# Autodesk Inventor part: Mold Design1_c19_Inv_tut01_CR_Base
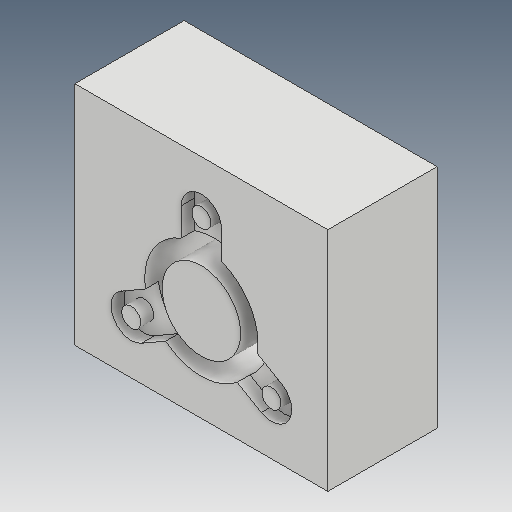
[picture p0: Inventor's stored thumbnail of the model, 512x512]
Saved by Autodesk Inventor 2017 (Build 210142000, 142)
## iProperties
Created: 2016-07
Part Number: Mold Design1_c19_Inv_tut01_CR_Base
Material: Generic
Document SubType Name: Modeling
Designer: Sandeep
Density: 1 g/cm^3
Appearance: Default
Author: Sandeep
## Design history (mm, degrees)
node "Mold Design1_c19_Inv_tut01_MP"
feature "Solid3::Mold Design1_c19_Inv_tut01_MP"
tag "TaggingFeature1"
body "Solid1"
feature "Mold Design1_c19_Inv_tut01_MP_Bodies"
